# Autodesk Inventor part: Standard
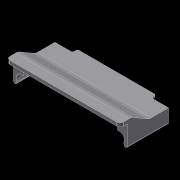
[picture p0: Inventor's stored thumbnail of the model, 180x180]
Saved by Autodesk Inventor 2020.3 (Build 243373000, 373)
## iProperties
RuleStatus: InUse
AfterDocSave0: file://Part Number Cleaner
Created: 2023-05
Material: Generic
Catalog Web Link: https://www.janelia.org/
Vendor: HHMI: JRC - jET
Document SubType Name: Modeling
Designer: sohna
Density: 1 g/cm^3
Appearance: Default
DESIGN DEPARTMENT: HHMI: JRC - jET
ALTERED ITEM PART NUMBER: N/A
ALTERED ITEM VENDOR: N/A
ALTERED ITEM DESCRIPTION: N/A
Title: Standard
Author: sohna
Revision Number: 0
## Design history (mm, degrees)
sketch "Sketch1"
  geometry: L1 (-2.464, 0)-(14.783, 0) reference; L2 (0, 8.636)-(0, -51.816) reference; L3 (12.319, 0)-(0, 0); L4 (12.319, 0)-(12.319, -10.16); L5 (12.319, -10.16)-(3.175, -25.998); L6 (3.175, -25.998)-(3.175, -43.18); L7 (3.175, -43.18)-(0, -43.18); L8 (0, 0)-(0, -43.18); L9 (9.144, 0)-(9.144, -6.35); L10 (9.144, -6.35)-(0, -6.35)
  constraints: 16 end point, 4 point on line, 3 perpendicular, 2 vertical, 1 collinear, 1 parallel
  dimensions: "d0" = 9.144 distance between parallel lines of L2 L9; "d1" = 36.83 distance between parallel lines of L7 L10; "d2" = 3.175 distance between parallel lines of L9 L4; "d3" = 3.175 distance of L6.end L7.end; "d4" = 10.16 distance of L3.start L4.end; "d6" = 30 deg angle of L6 L5; "d7" = 6.35 distance between parallel lines of L10 L1
extrude "Extrusion1" new body sketch "Sketch1" stored distance "d8" = 101.092; taper "d9" = 0 deg
sketch "Sketch2"
  geometry: L1 (0, 0)-(101.092, 0) reference; L2 (0, -3.175)-(0, 0) reference; L3 (101.092, -3.175)-(0, -3.175) reference; L4 (101.092, 0)-(101.092, -3.175) reference; L5 (50.546, -17.545)-(50.546, 13.592) reference; L6 (-20.853, -3.175)-(121.416, -3.175) reference; L7 (0, -3.175)-(0, -10.795); L8 (0, -10.795)-(3.048, -10.795); L9 (3.048, -10.795)-(3.048, -9.317); L10 (0, 5.969)-(0, -3.175) reference; L11 (0, -3.175)-(6.54, -3.175); L12 (101.092, -3.175)-(0, -3.175) reference; L13 (3.048, -10.795)-(1.975, -13.097); L14 (1.975, -13.097)-(-0.529, -11.93); L15 (-0.529, -11.93)-(0, -10.795); L16 (0, -10.795)-(0, -12.176); C1 r 4.064 at (94.552, -7.239); A1 r 4.064 centre (6.54, -7.239) between (3.048, -9.317) and (6.54, -3.175); A2 r 4.064 centre (6.54, -7.239) between (6.54, -3.175) and (3.048, -9.317); 2 further points
  constraints: 16 end point, 4 point on circle, 3 centre point, 3 perpendicular, 2 equal radius, 2 point on line, 2 tangent, 2 vertical, 1 parallel, 1 symmetric about line
  dimensions: "d10" = 8.128 diameter of A1; "d11" = 88.011 distance of C1.centre A1.centre; "d12" = 7.62 distance between parallel lines of L8 L11; "d13" = 47.498 distance between parallel lines of L5 L9; "d14" = 25 deg angle of L9 L13; "d15" = 2.54 distance of L8.end L13.end
extrude "Extrusion2" join sketch "Sketch2" stored distance "d16" = 25.4; taper "d17" = 0 deg
mirror "Mirror1"
fillet "Fillet1" dims "d18" = 3.175
fillet "Fillet2" dims "d19" = 0.762
sketch "Sketch3"
  geometry: L1 (9.144, -6.35)-(9.144, 0) reference; L2 (0, -43.18)-(0, -6.35) reference; L3 (9.144, -6.35)-(-8.516, -6.35) reference; L4 (9.144, -6.35)-(0, -22.188); L5 (12.319, -10.16)-(3.175, -25.998) reference; 1 further point
  constraints: 2 end point, 1 parallel, 1 point on line
extrude "Extrusion3" cut sketch "Sketch3" stored distance "d20" = 83.82; taper "d21" = 0 deg
fillet "Fillet3" dims "d22" = 3.175
sketch "Sketch5"
  geometry: L1 (101.092, 0)-(101.092, -11.691) reference; L2 (0, 0)-(101.092, 0) reference; L3 (0, 0)-(0, -11.691) reference; L4 (0.44, -12.381)-(1.284, -12.775) reference; L5 (2.297, -12.406)-(2.751, -11.433) reference; L6 (3.048, -10.091)-(3.048, -10.058) reference; L7 (94.552, -3.175)-(6.54, -3.175) reference; L8 (98.044, -10.091)-(98.044, -10.058) reference; L9 (98.795, -12.406)-(98.341, -11.433) reference; L10 (100.652, -12.381)-(99.808, -12.775) reference; L11 (101.092, 0)-(0, 0) reference; L12 (15.621, 0)-(85.471, 0); L13 (85.471, 0)-(85.471, -1.524); L14 (85.471, -1.524)-(15.621, -1.524); L15 (15.621, -1.524)-(15.621, 0); L16 (50.546, -17.41)-(50.546, 13.57) reference; A1 r 0.762 centre (100.33, -11.691) between (100.652, -12.381) and (101.092, -11.691) reference; A2 r 0.762 centre (0.762, -11.691) between (0, -11.691) and (0.44, -12.381) reference; A3 r 0.762 centre (1.606, -12.084) between (1.284, -12.775) and (2.297, -12.406) reference; A4 r 3.175 centre (-0.127, -10.091) between (2.751, -11.433) and (3.048, -10.091) reference; A5 r 3.175 centre (-0.127, -10.058) between (3.048, -10.058) and (2.797, -8.822) reference; A6 r 4.064 centre (6.54, -7.239) between (6.54, -3.175) and (2.797, -8.822) reference; A7 r 4.064 centre (94.552, -7.239) between (98.295, -8.822) and (94.552, -3.175) reference; A8 r 3.175 centre (101.219, -10.058) between (98.295, -8.822) and (98.044, -10.058) reference; A9 r 3.175 centre (101.219, -10.091) between (98.044, -10.091) and (98.341, -11.433) reference; A10 r 0.762 centre (99.486, -12.084) between (98.795, -12.406) and (99.808, -12.775) reference; 3 further points
  constraints: 8 end point, 2 parallel, 1 horizontal, 1 perpendicular, 1 point on line, 1 other
  dimensions: "d27" = 1.524 distance of L12.end L13.end; "d28" = 69.85 distance between parallel lines of L13 L15
extrude "Extrusion5" join sketch "Sketch5" distance "d29" = 4.445; taper "d30" = 0 deg
fillet "Fillet4" dims "d31" = 1.524
sketch "Sketch6"
  geometry: L1 (1.651, -43.18)-(3.175, -43.18) reference; L2 (3.175, -43.18)-(1.651, -43.18) reference; L3 (3.175, -43.18)-(-8.516, -43.18) reference; L4 (-9.206, -43.18)-(-8.516, -43.18) reference; L5 (-9.206, -43.18)-(-9.6, -43.18) reference; L6 (-9.231, -43.18)-(-9.6, -43.18) reference; L7 (-9.231, -43.18)-(-8.258, -43.18) reference; L8 (-6.916, -43.18)-(-8.258, -43.18) reference; L9 (-6.916, -43.18)-(-6.883, -43.18) reference; L10 (-5.647, -43.18)-(-6.883, -43.18) reference; L11 (-5.647, -43.18)-(0, -43.18) reference; L12 (-5.647, -43.18)-(0, -43.18) reference; L13 (-6.883, -43.18)-(-5.647, -43.18) reference; L14 (-6.916, -43.18)-(-6.883, -43.18) reference; L15 (-8.258, -43.18)-(-6.916, -43.18) reference; L16 (-9.231, -43.18)-(-8.258, -43.18) reference; L17 (-9.6, -43.18)-(-9.231, -43.18) reference; L18 (-9.206, -43.18)-(-9.6, -43.18) reference; L19 (-8.516, -43.18)-(-9.206, -43.18) reference; L20 (3.175, -43.18)-(-8.516, -43.18) reference; L21 (0, -15.838)-(0, -6.35) reference; L22 (0, -43.18)-(0, -6.35) reference; L23 (0, -6.35)-(0, -43.18) reference; L24 (0, -6.35)-(0, -15.838) reference; L25 (0, -22.188)-(0, -15.838) reference; L26 (0, -15.838)-(0, -22.188) reference; L27 (1.651, -47.625)-(1.651, -46.101) reference; L28 (1.651, -46.101)-(1.651, -47.625) reference; L29 (1.651, -43.18)-(1.651, -44.704) reference; L30 (1.651, -44.704)-(1.651, -43.18) reference; L31 (1.651, -43.18)-(0, -40.32); L32 (1.651, -44.704)-(1.651, -46.101) reference; L33 (1.651, -44.704)-(1.651, -46.101) reference; 4 further points
  constraints: 2 end point, 1 point on line
  dimensions: "d32" = 60 deg angle of L31 L3
extrude "Extrusion6" cut sketch "Sketch6" stored distance "d33" = 76.2; taper "d34" = 0 deg
fillet "Fillet5" dims "d35" = 3.175
fillet "Fillet6" dims "d36" = 6.35
body "Solid1"
node "Projected Loop1"
node "Projected Loop2"
node "Projected Loop3"
node "Projected Loop4"
node "Projected Loop5"
